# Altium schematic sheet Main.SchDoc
size 384 x 574 mm; SheetNumber: 1
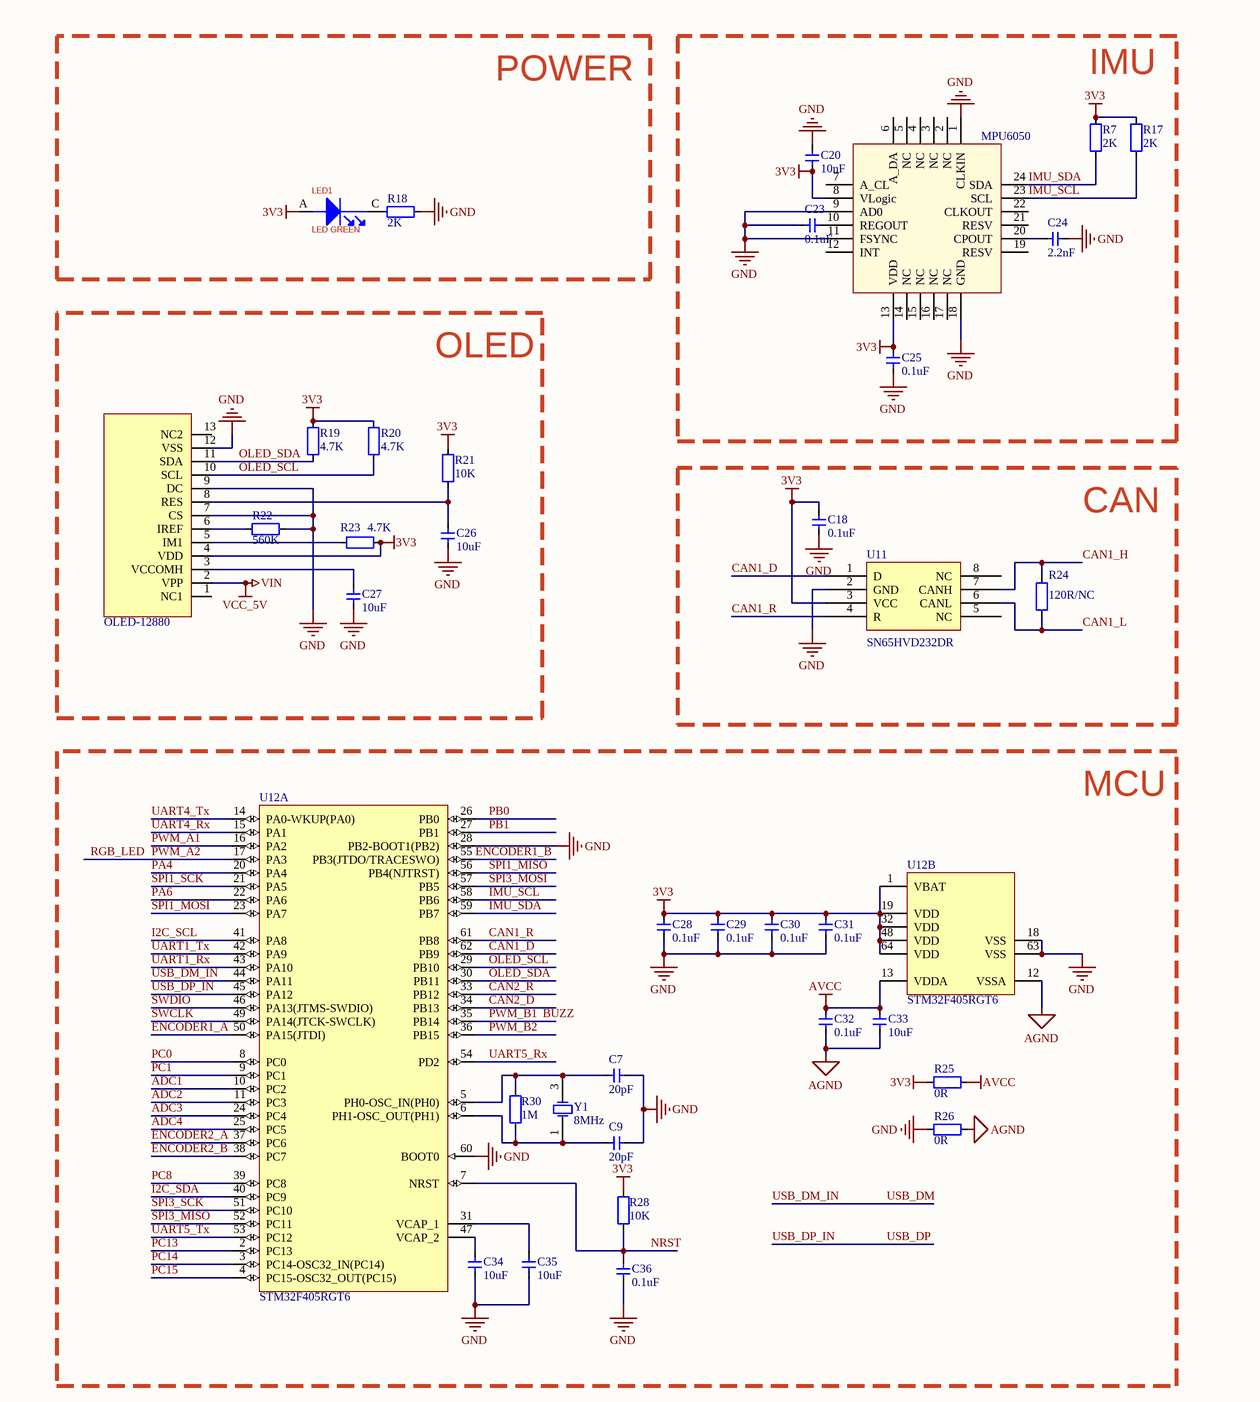
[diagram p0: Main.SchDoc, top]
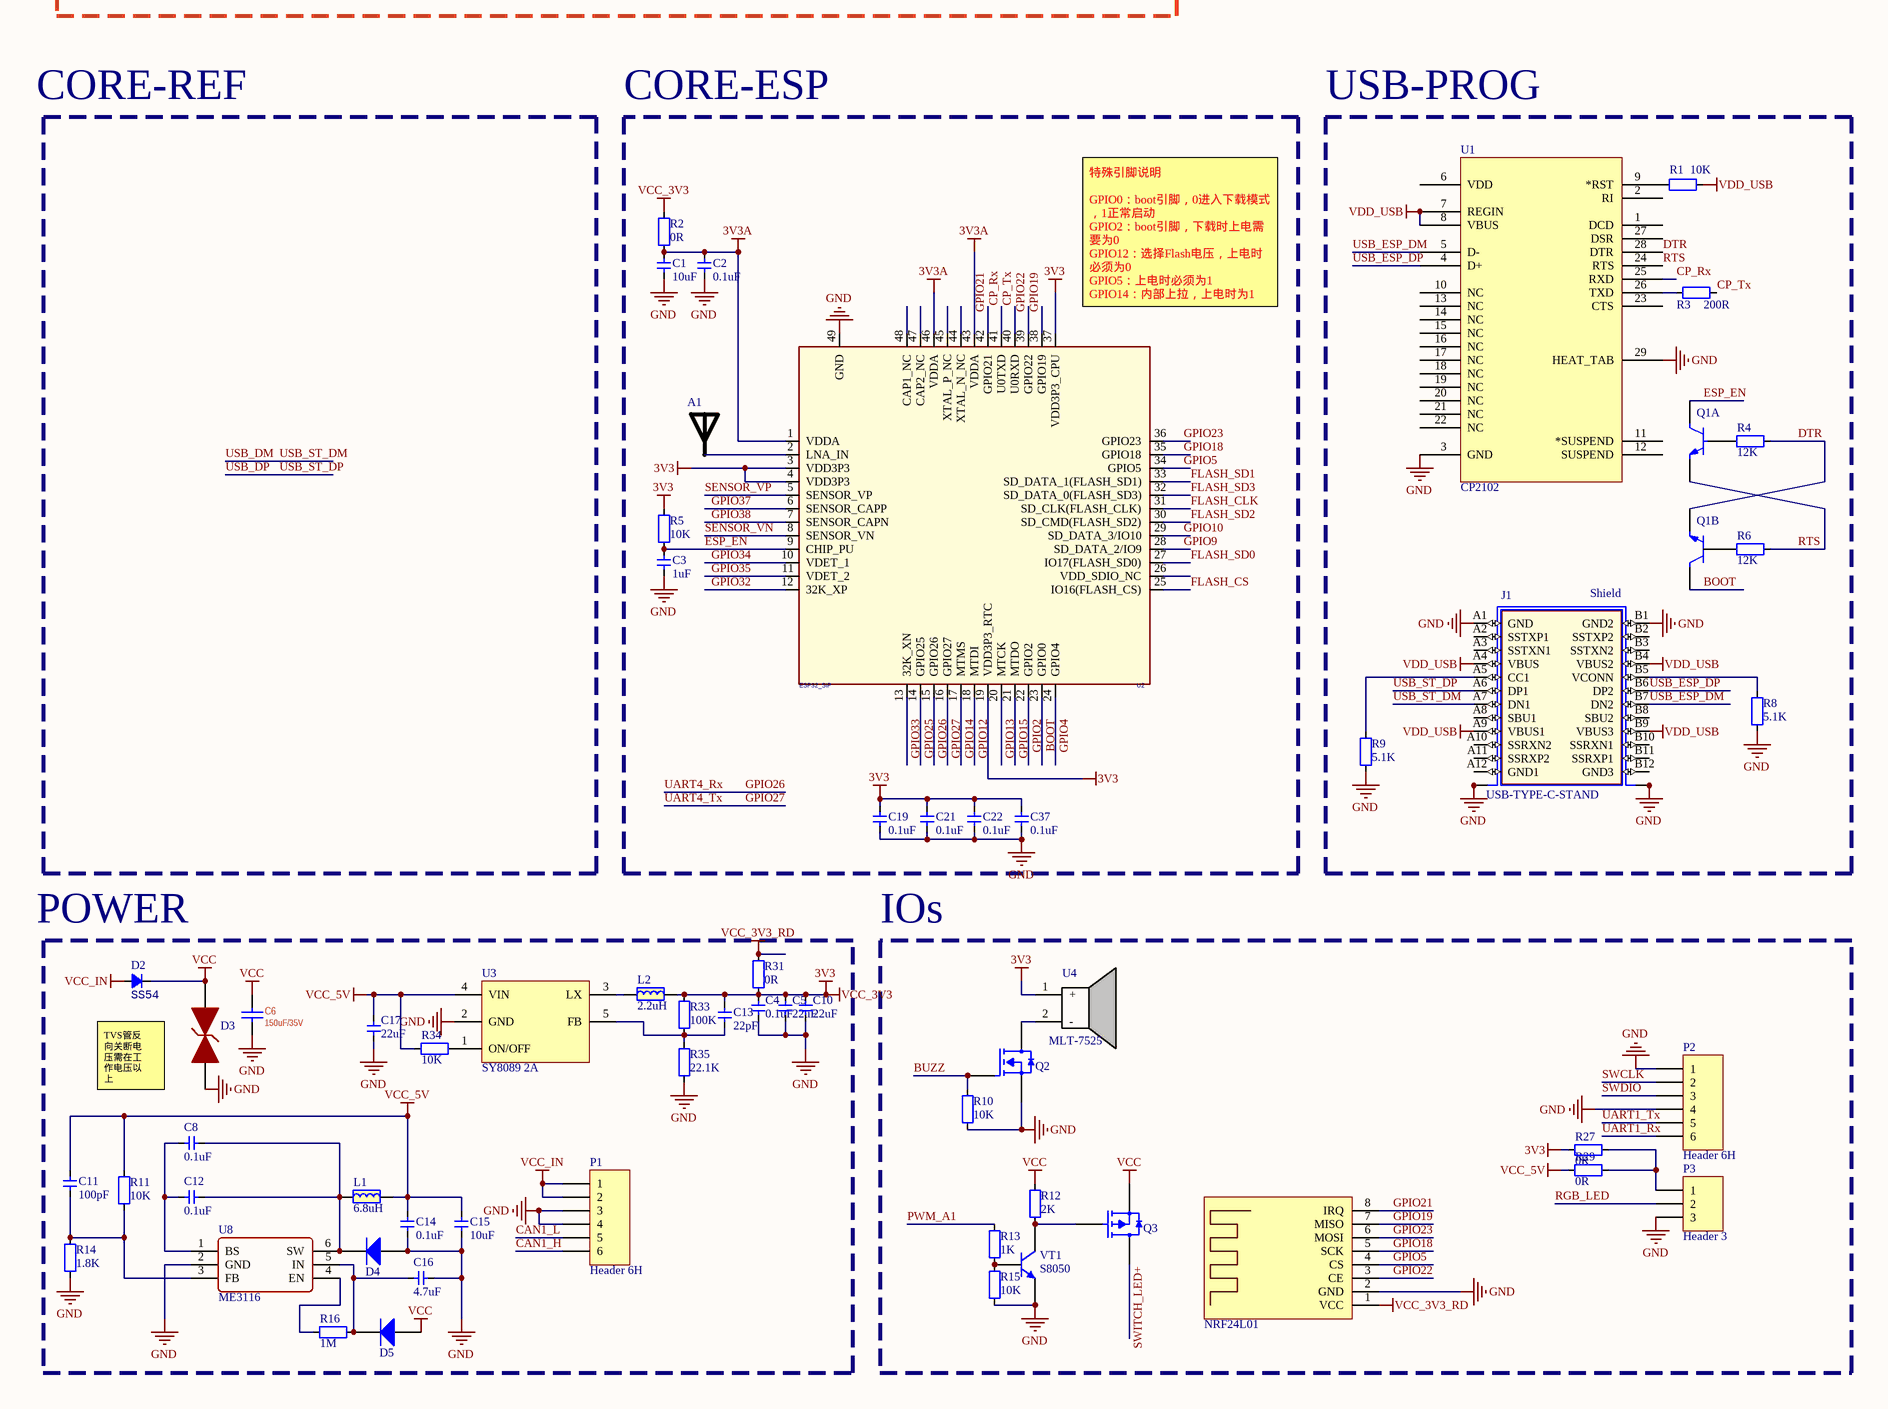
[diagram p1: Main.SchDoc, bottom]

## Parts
1  OLED-12880  [OLED-12880]
A1  RAINSUN  [ANT-Rainsun-AN5120]  (value not drawn)
C1  10uF  [CAP_0402]
C2  0.1uF  [CAP_0402]
C3  1uF  [CAP_0402]
C4  0.1uF  [CAP_0402]
C5  22uF  [C0603]
C6  value 150uF/35V  [CAP-SMD_BD8.0-L8.3-W8.3-LS9.3-FD]  (hidden comment: 220uF/25V)
C7  20pF  [CAP_0402]
C8  0.1uF  [CAP_0402]
C9  20pF  [CAP_0402]
C10  22uF  [C0603]
C11  100pF  [CAP_0402]
C12  0.1uF  [CAP_0402]
C13  22pF  [CAP_0402]
C14  0.1uF  [CAP_0402]
C15  10uF  [CAP_0402]
C16  4.7uF  [C0603]
C17  22uF  [C0603]
C18  0.1uF  [CAP_0402]
C19  0.1uF  [CAP_0402]
C20  10nF  [CAP_0402]
C21  0.1uF  [CAP_0402]
C22  0.1uF  [CAP_0402]
C23  0.1uF  [CAP_0402]
C24  2.2nF  [CAP_0402]
C25  0.1uF  [CAP_0402]
C26  10uF  [CAP_0402]
C27  10uF  [CAP_0402]
C28  0.1uF  [CAP_0402]
C29  0.1uF  [CAP_0402]
C30  0.1uF  [CAP_0402]
C31  0.1uF  [CAP_0402]
C32  0.1uF  [CAP_0402]
C33  10uF  [CAP_0402]
C34  10uF  [CAP_0402]
C35  10uF  [CAP_0402]
C36  0.1uF  [CAP_0402]
C37  0.1uF  [CAP_0402]
D2  SS54  [DO-214AC]
D3  SMBJ28CA  [SMBJ-CA_MFG]  (value not drawn)
D4  二极管-5819W  [SOD-323]  (value not drawn)
D5  二极管-5819W  [SOD-323]  (value not drawn)
J1  USB-TYPE-C-STAND  [USB-TYPE-C-STAND]
L1  6.8uH  [IND-201612]
L2  2.2uH  [IND-252012A-2R2]
LED1  LED GREEN  [LED-0603]
P1  Header 6H  [CONN-TH_HC-ZH1.5-6A]
P2  Header 6H  [CONN-TH_HC-ZH1.5-6A-s]
P3  Header 3  [CONN-TH_HC-ZH1.5-3A-S]
Q1  BC847BVC-7  [SOT563-6]  (value not drawn)  (parts A,B of 2)
Q2  AO3400A  [SOT23-3]  (value not drawn)
Q3  AO3401A  [SOT23-3]  (value not drawn)
R1  10K  [RES_0402_1]
R2  0R  [RES_0402_1]
R3  200R  [RES_0402_1]
R4  12K  [RES_0402_1]
R5  10K  [RES_0402_1]
R6  12K  [RES_0402_1]
R7  2K  [RES_0402_1]
R8  5.1K  [RES_0402_1]
R9  5.1K  [RES_0402_1]
R10  10K  [RES_0402_1]
R11  10K  [RES_0402_1]
R12  2K  [RES_0402_1]
R13  1K  [RES_0402_1]
R14  1.8K  [RES_0402_1]
R15  10K  [RES_0402_1]
R16  1M  [RES_0402_1]
R17  2K  [RES_0402_1]
R18  2K  [RES_0402_1]
R19  4.7K  [RES_0402_1]
R20  4.7K  [RES_0402_1]
R21  10K  [RES_0402_1]
R22  560K  [RES_0402_1]
R23  4.7K  [RES_0402_1]
R24  120R/NC  [RES_0402_1]
R25  0R  [RES_0402_1]
R26  0R  [RES_0402_1]
R27  0R  [RES_0402_1]
R28  10K  [RES_0402_1]
R29  0R  [RES_0402_1]
R30  1M  [RES_0402]
R31  0R  [RES_0402_1]
R33  100K  [RES_0402_1]
R34  10K  [RES_0402_1]
R35  22.1K  [RES_0402_1]
U1  CP2102  [QFN-28]
U2  ESP32_SIP  [QFN-48_7X7]
U3  SY8089 2A  [SOT23-5]
U4  MLT-7525  [BUZ-SMD_4P-L7.5-W7.5-P7.59-TL]
U7  NRF24L01  [NRF24L01-MODULE]
U8  ME3116  [SOT23-6]
U10  MPU6050  [QFN-24]
U11  Manufacturer Part Number: SN65HVD232DR  [SO-8]  (hidden comment: SN65HVD232D)
U12  STM32F405RGT6  [LQFP-64_N]  (parts A,B of 2)
VT1  S8050  [SMT_TRIODE_NPN]
Y1  value 8MHz  [LC-SMD-3225_4P]  (hidden comment: XTAL-4)

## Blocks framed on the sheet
POWER: LED1 R18
IMU: C20 C23-C25 R7 R17 U10
OLED: 1 C26 C27 R19-R23
CAN: C18 R24 U11
MCU: C7 C9 C28-C36 R25 R26 R28 R30 U12 Y1
CORE-ESP: A1 C1-C3 C19 C21 C22 C37 R2 R5 U2
USB-PROG: J1 Q1 R1 R3 R4 R6 R8 R9 U1
IOs: P2 P3 Q2 Q3 R10 R12 R13 R15 R27 R29 U4 U7 VT1

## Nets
3V3: 1.4(VDD) C4.2 C5.2 C10.2 C13.2 C18.2 C19.2 C20.1 C21.2 C22.2 C25.2 C28.2 C29.2 C30.2 C31.2 C37.2 L2.2 LED1.A(ANODE) R2.1 R5.1 R7.2 R17.2 R19.2 R20.2 R21.2 R23.2 R25.2 R27.2 R28.2 R31.1 R33.2 U2.3(VDD3P3) U2.4(VDD3P3) U2.19(VDD3P3_RTC) U2.37(VDD3P3_CPU) U4.1(+) U10.8(VLogic) U10.13(VDD) U11.3(VCC) U12.1(VBAT) U12.19(VDD) U12.32(VDD) U12.48(VDD) U12.64(VDD)  [also labelled VCC_3V3]
3V3A: C1.2 C2.2 R2.2 U2.1(VDDA) U2.43(VDDA) U2.46(VDDA)
AGND: C32.1 C33.1 R26.1 U12.12(VSSA)
AVCC: C32.2 C33.2 R25.1 U12.13(VDDA)
GND: 1.7(CS) 1.9(DC) 1.12(VSS) C1.1 C2.1 C3.2 C4.1 C5.1 C6.2 C7.2 C9.2 C10.1 C14.1 C15.1 C16.1 C17.1 C18.1 C19.1 C20.2 C21.1 C22.1 C23.2 C24.1 C25.1 C26.1 C27.1 C28.1 C29.1 C30.1 C31.1 C34.1 C35.1 C36.1 C37.1 D3.1 D4.1(A) J1.A1(GND) J1.B1(GND2) J1.S1(SHIELD) J1.S2(SHIELD) J1.S3(SHIELD1) J1.S4(SHIELD1) P1.3 P1.4 P2.1 P2.4 P3.3 Q2.2(S) R8.2 R9.2 R10.1 R14.1 R15.2 R18.1 R22.2 R26.2 R35.1 U1.3(GND) U1.29(HEAT_TAB) U2.49(GND) U3.2(GND) U7.2(GND) U8.2(GND) U10.1(CLKIN) U10.9(AD0) U10.11(FSYNC) U10.18(GND) U11.2(GND) U12.18(VSS) U12.28(PB2-BOOT1(PB2)) U12.60(BOOT0) U12.63(VSS) VT1.2(E)
VCC: C6.1 D2.2(K) D3.2 D5.1(A) Q3.2(S) R12.2
VCC_3V3_RD: R31.2 U7.1(VCC)
VCC_5V: 1.2(VPP) C11.1 C14.2 C15.2 C17.2 L1.2 R11.2 R29.2 R34.2 U3.4(VIN)  [also labelled VIN]
VCC_IN: D2.1(A) P1.1 P1.2
VDD_USB: J1.A4(VBUS) J1.A9(VBUS1) J1.B4(VBUS2) J1.B9(VBUS3) R1.1 U1.7(REGIN) U1.8(VBUS)
ADC1: U12.10(PC2)
ADC2: U12.11(PC3)
ADC3: U12.24(PC4)
ADC4: U12.25(PC5)
BOOT: Q1.3(C2) U2.23(GPIO0)
BUZZ: Q2.1(G) R10.2 U12.35(PB14)  [also labelled PWM_B1]
CAN1_D: U11.1(D) U12.62(PB9)
CAN1_H: P1.6 R24.1 U11.7(CANH)
CAN1_L: P1.5 R24.2 U11.6(CANL)
CAN1_R: U11.4(R) U12.61(PB8)
CAN2_D: U12.34(PB13)
CAN2_R: U12.33(PB12)
CP_Rx: U1.25(RXD) U2.41(U0TXD)
CP_Tx: R3.1 U2.40(U0RXD)
DTR: Q1.4(E2) R4.1 U1.28(DTR)
ENCODER1_A: U12.50(PA15(JTDI))
ENCODER1_B: U12.55(PB3(JTDO/TRACESWO))
ENCODER2_A: U12.37(PC6)
ENCODER2_B: U12.38(PC7)
ESP_EN: C3.1 Q1.6(C1) R5.2 U2.9(CHIP_PU)
FLASH_CLK: U2.31(SD_CLK(FLASH_CLK))
FLASH_CS: U2.25(IO16(FLASH_CS))
FLASH_SD0: U2.27(IO17(FLASH_SD0))
FLASH_SD1: U2.33(SD_DATA_1(FLASH_SD1))
FLASH_SD2: U2.30(SD_CMD(FLASH_SD2))
FLASH_SD3: U2.32(SD_DATA_0(FLASH_SD3))
GPIO2: U2.22(GPIO2)
GPIO4: U2.24(GPIO4)
GPIO5: U2.34(GPIO5) U7.4(CS)
GPIO9: U2.28(SD_DATA_2/IO9)
GPIO10: U2.29(SD_DATA_3/IO10)
GPIO12: U2.18(MTDI)
GPIO13: U2.20(MTCK)
GPIO14: U2.17(MTMS)
GPIO15: U2.21(MTDO)
GPIO18: U2.35(GPIO18) U7.5(SCK)
GPIO19: U2.38(GPIO19) U7.7(MISO)
GPIO21: U2.42(GPIO21) U7.8(IRQ)
GPIO22: U2.39(GPIO22) U7.3(CE)
GPIO23: U2.36(GPIO23) U7.6(MOSI)
GPIO25: U2.14(GPIO25)
GPIO26: U2.15(GPIO26) U12.15(PA1)  [also labelled UART4_Rx]
GPIO27: U2.16(GPIO27) U12.14(PA0-WKUP(PA0))  [also labelled UART4_Tx]
GPIO32: U2.12(32K_XP)
GPIO33: U2.13(32K_XN)
GPIO34: U2.10(VDET_1)
GPIO35: U2.11(VDET_2)
GPIO37: U2.6(SENSOR_CAPP)
GPIO38: U2.7(SENSOR_CAPN)
I2C_SCL: U12.41(PA8)
I2C_SDA: U12.40(PC9)
IMU_SCL: R17.1 U10.23(SCL) U12.58(PB6)
IMU_SDA: R7.1 U10.24(SDA) U12.59(PB7)
NRST: C36.2 R28.1 U12.7(NRST)
OLED_SCL: 1.10(SCL) R20.1 U12.29(PB10)
OLED_SDA: 1.11(SDA) R19.1 U12.30(PB11)
PA4: U12.20(PA4)
PA6: U12.22(PA6)
PB0: U12.26(PB0)
PB1: U12.27(PB1)
PC0: U12.8(PC0)
PC1: U12.9(PC1)
PC8: U12.39(PC8)
PC13: U12.2(PC13)
PC14: U12.3(PC14-OSC32_IN(PC14))
PC15: U12.4(PC15-OSC32_OUT(PC15))
PWM_A1: R13.1 U12.16(PA2)
PWM_A2: P3.2 U12.17(PA3)  [also labelled RGB_LED]
PWM_B2: U12.36(PB15)
RTS: Q1.1(E1) R6.1 U1.24(RTS)
SENSOR_VN: U2.8(SENSOR_VN)
SENSOR_VP: U2.5(SENSOR_VP)
SPI1_MISO: U12.56(PB4(NJTRST))
SPI1_MOSI: U12.23(PA7)
SPI1_SCK: U12.21(PA5)
SPI3_MISO: U12.52(PC11)
SPI3_MOSI: U12.57(PB5)
SPI3_SCK: U12.51(PC10)
SWCLK: P2.2 U12.49(PA14(JTCK-SWCLK))
SWDIO: P2.3 U12.46(PA13(JTMS-SWDIO))
SWITCH_LED+: Q3.3(D)
UART1_Rx: P2.6 U12.43(PA10)
UART1_Tx: P2.5 U12.42(PA9)
UART5_Rx: U12.54(PD2)
UART5_Tx: U12.53(PC12)
USB_DM: J1.A7(DN1) U12.44(PA11)  [also labelled USB_DM_IN, USB_ST_DM]
USB_DP: J1.A6(DP1) U12.45(PA12)  [also labelled USB_DP_IN, USB_ST_DP]
USB_ESP_DM: J1.B7(DN2) U1.5(D-)
USB_ESP_DP: J1.B6(DP2) U1.4(D+)
Net1_3: 1.3(VCCOMH) C27.2
Net1_5: 1.5(IM1) R23.1
Net1_6: 1.6(IREF) R22.1
Net1_8: 1.8(RES) C26.2 R21.1
NetA1_1: A1.1 U2.2(LNA_IN)
NetC7_1: C7.1 R30.1 U12.5(PH0-OSC_IN(PH0)) Y1.3(OSC2)
NetC8_1: C8.1 C12.1 D4.2(K) L1.1 U8.6(SW)
NetC8_2: C8.2 C12.2 U8.1(BS)
NetC9_1: C9.1 R30.2 U12.6(PH1-OSC_OUT(PH1)) Y1.1(OSC1)
NetC11_2: C11.2 R11.1 R14.2 U8.3(FB)
NetC13_1: C13.1 R33.1 R35.2 U3.5(FB)
NetC16_2: C16.2 D5.2(K) R16.1 U8.5(IN)
NetC23_1: C23.1 U10.10(REGOUT)
NetC24_2: C24.2 U10.20(CPOUT)
NetC34_2: C34.2 U12.47(VCAP_2)
NetC35_2: C35.2 U12.31(VCAP_1)
NetJ1_A5: J1.A5(CC1) R9.1
NetJ1_B5: J1.B5(VCONN) R8.1
NetL2_1: L2.1 U3.3(LX)
NetLED1_C: LED1.C(CATHODE) R18.2
NetP3_1: P3.1 R27.1 R29.1
NetQ1_2: Q1.2(B1) R4.2
NetQ1_5: Q1.5(B2) R6.2
NetQ2_3: Q2.3(D) U4.2(-)
NetQ3_1: Q3.1(G) R12.1 VT1.3(C)
NetR1_2: R1.2 U1.9(*RST)
NetR3_2: R3.2 U1.26(TXD)
NetR13_2: R13.2 R15.1 VT1.1(B)
NetR16_2: R16.2 U8.4(EN)
NetR34_1: R34.1 U3.1(ON/OFF)

Not connected (* = marked no-connect by the designer): 1 1(NC1) 13(NC2); J1 A2(SSTXP1) A3(SSTXN1) A8(SBU1) A10(SSRXN2) A11(SSRXP2) A12(GND1) B2(SSTXP2) B3(SSTXN2) B8(SBU2) B10(SSRXN1) B11(SSRXP1) B12(GND3); U1 1(DCD) 2(RI) 6(VDD) 10(NC) 11(*SUSPEND) 12(SUSPEND) 13(NC) 14(NC) 15(NC) 16(NC) 17(NC) 18(NC) 19(NC) 20(NC) 21(NC) 22(NC) 23(CTS) 27(DSR); U2 26(VDD_SDIO_NC) 44(XTAL_N_NC) 45(XTAL_P_NC) 47(CAP2_NC) 48(CAP1_NC); U10 2(NC) 3(NC) 4(NC) 5(NC) 6(A_DA) 7(A_CL) 12(INT) 14(NC) 15(NC) 16(NC) 17(NC) 19(RESV) 21(RESV) 22(CLKOUT); U11 5(NC) 8(NC)

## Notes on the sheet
- CORE-REF
- (near U2) 特殊引脚说明
  GPIO0：boot引脚，0进入下载模式，1正常启动
  GPIO2：boot引脚，下载时上电需要为0
  GPIO12：选择Flash电压，上电时必须为0
  GPIO5：上电时必须为1
  GPIO14：内部上拉，上电时为1
  GPIO15：上电时必须为1
- (near D2) POWER
- TVS管反
  向关断电
  压需在工
  作电压以
  上

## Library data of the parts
A1 = ANT-Rainsun-AP5120
C1-C4 C8 C11 C12 C14 C15 C18-C37 = 电容-0402: Capacitor; Value: 0.1u
C5 C7 C9 C10 C13 C17 = 电容-0402: Capacitor
C6 = CAP: Capacitor, chip, ceramic; Parameters: E22 CAP; PN: RVT1E221M0607
C16 = 电容-0402: Capacitor; Value: 4.7uF 35V
D2 = Diode_SMA: Diode; Type: SMA
D4 D5 = 二极管-5819W: 40V
J1 = USB-TYPE-C-STAND: MP: 632722110112; MF: Wurth Electronics
L1 L2 = 电感-201612
LED1 = LED: LED GRN SGL RA 25mA 4.1V SMD; CLASS: IC; CAD_APPROVED: Yes; MFG_PN01: AA4040ZGS; MFG_NAME01: Kingbright; AGILE_PN: 370-76642; PN: 19-217/G7C-AN1P2/3T
P1 P2 = Header 6H: Header, 6-Pin, Right Angle
P3 = Header 3: Header, 3-Pin
Q2 = AO3400A: N-MOS
Q3 = AO3401A: P-MOS
R1-R26 R28 R30 R34 = 电阻-0402: Resistor; Value: 22R
R27 R29 R31 R33 R35 = 电阻-0402: Resistor
U1 = CP2102: USB转TTL; PART DESC: SINGLE-CHIP USB TO UART BRIDGE, QFN28, RoHS.; MFG #1: SILICON LABS
U2 = ESP32-PICO
U3 = SY8089: LDO
U4 = DET402
U7 = NRF24L01模块
U8 = ME3116: DC-DC
U10 = MPU6050: 六轴传感器
U11 = SN65HVD232D: Manufacturer: Texas Instruments; Protocol: CAN; Number of Drivers/Receivers: 1/1; Duplex: Half; Data Rate: 1Mbps; Voltage - Supply: 3 V ~ 3.6 V
U12 = STM32F405RGT6: ARM Cortex-M4 32-bit MCU+FPU, 210 DMIPS, 1024 kB Flash, 192 kB Internal RAM, 51 I/Os, 64-pin LQFP, -40 to 85 degC, Tray; Manufacturer: STMicroelectronics; D/A Converter: 2x12-bit; FLASH Size (Prog) (kB): 1024; I/Os (High Current): 51; Internal RAM Size (kB): 192; Operating Frequency(F) (Processor speed) (MHz): 168; Supply Voltage(Vcc) max (V): 3.6; Supply Voltage(Vcc) min (V): 1.8
VT1 = SMT_TRIODE_NPN: Surface mount NPN transistor, package SOT-23
Y1 = XTAL-4: Crystal; Parameters: 20ppm 20pF -20/+70C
